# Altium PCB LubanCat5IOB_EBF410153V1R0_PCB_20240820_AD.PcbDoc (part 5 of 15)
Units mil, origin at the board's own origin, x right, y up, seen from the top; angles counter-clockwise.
Board outline 6811.02 x 4055.12 mil, 6 copper layers (TOP, GND02, ART03, ART04, PWR05, BOTTOM), stack 59.279 mil thick; 981 components, 783 nets, 3627 pads, 2669 vias.
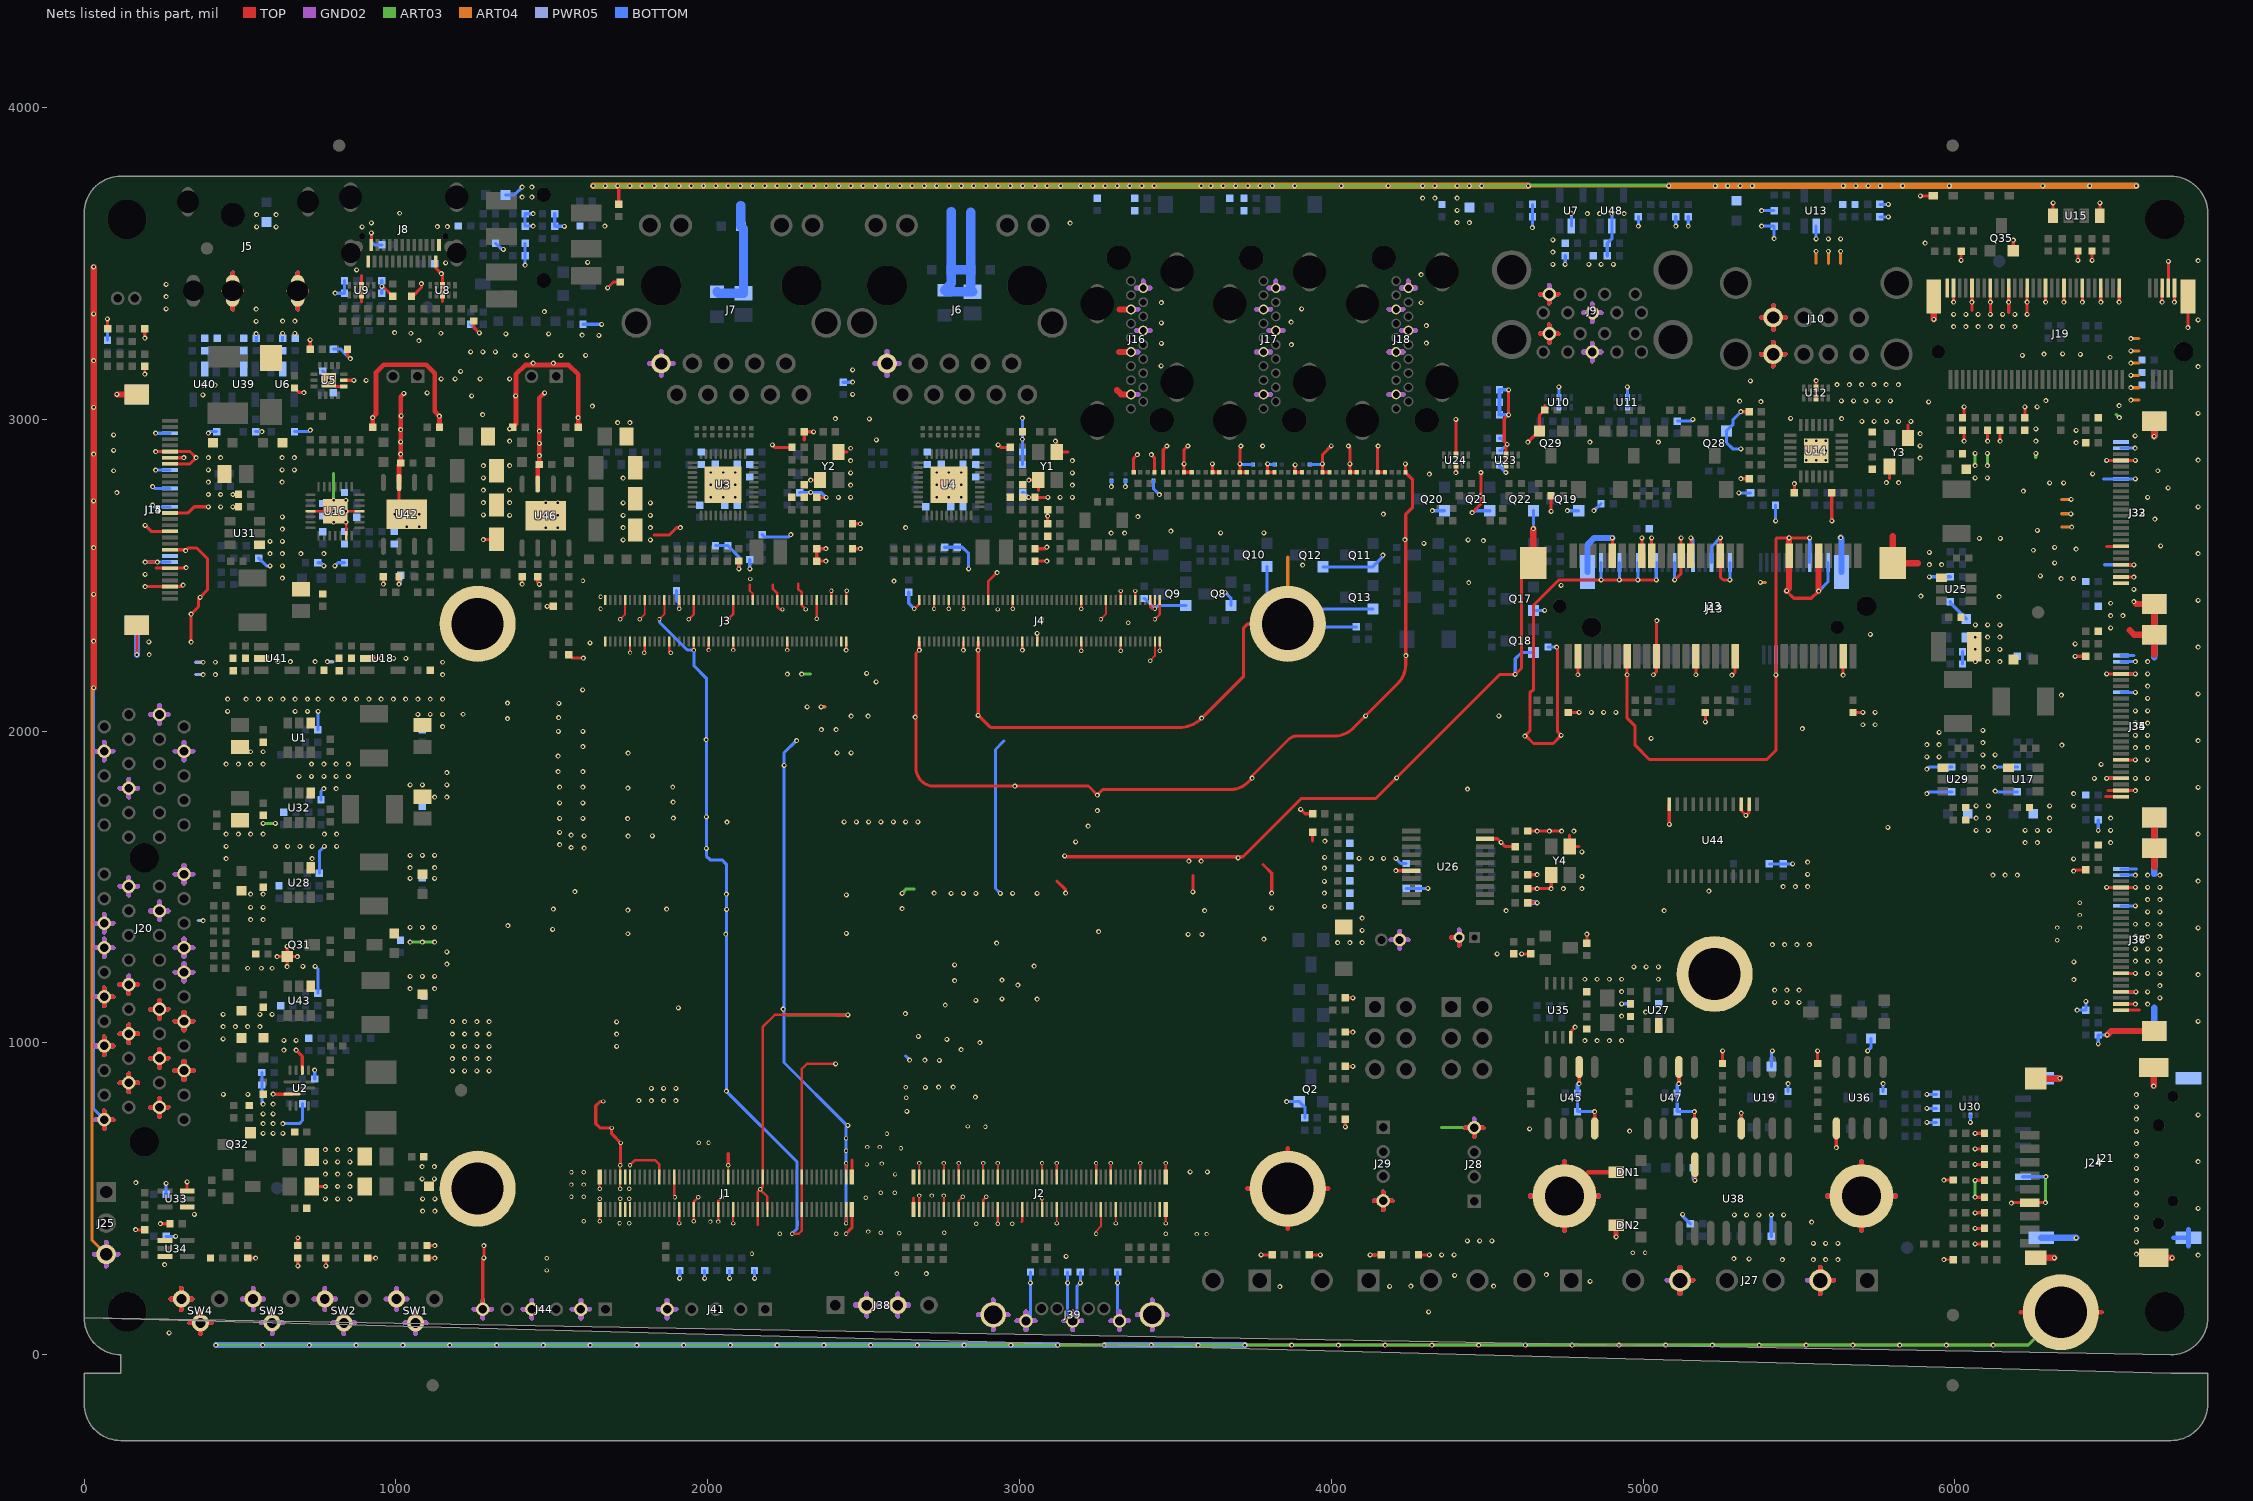
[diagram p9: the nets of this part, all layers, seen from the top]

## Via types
v1: diameter 16, hole 8, TOP to BOTTOM, 2357 vias
v2: diameter 14, hole 8, TOP to BOTTOM, 308 vias
v3: diameter 20, hole 10, TOP to BOTTOM, 4 vias

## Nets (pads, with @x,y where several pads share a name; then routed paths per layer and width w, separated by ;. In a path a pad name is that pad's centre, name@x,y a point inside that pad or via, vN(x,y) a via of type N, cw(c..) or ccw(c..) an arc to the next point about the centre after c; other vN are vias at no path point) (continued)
GND: C1.2 C2.2 C3.2 C4.2 C5.2 C8.2 C9.2 C10.2 C11.2 C12.2 C13.2 C15.2 C17.2 C18.2 C19.2 C21.2 C22.2 C23.2 C24.2 C25.2 C26.2 C27.2 C28.2 C29.2 C30.2 C31.2 C32.2 C33.2 C34.2 C35.2 C36.2 C37.2 C38.2 C39.2 C40.2 C41.2 C42.2 C43.2 C44.2 C45.2 C46.2 C47.2 C48.2 C49.2 C50.2 C51.2 C52.2 C53.2 C54.2 C55.2 C56.2 C57.2 C58.2 C59.2 C60.2 C61.2 C62.2 C63.2 C64.2 C65.2 C66.2 C67.2 C68.2 C69.2 C70.2 C71.2 C72.2 C73.2 C74.2 C77.2 C78.2 C81.2 C86.2 C87.2 C88.2 C89.2 C90.2 C91.2 C92.2 C93.2 C94.2 C95.2 C96.2 C97.2 C98.2 C99.2 C100.2 C101.2 C102.2 C103.2 C104.2 C105.2 C106.2 C107.2 C108.2 C109.2 C110.2 C111.2 C114.2 C116.2 C118.2 C119.2 C120.2 C121.2 C123.2 C124.2 C125.2 C129.2 C130.2 C141.2 C153.2 C155.2 C158.2 C159.2 C160.2 C161.2 C162.2 C163.2 C164.2 C165.2 C166.2 C167.2 C168.2 C169.2 C170.2 C171.2 C172.2 C173.2 C174.2 C180.2 C181.2 C182.2 C183.2 C184.2 C185.2 C186.2 C187.2 C188.2 C193.2 C195.2 C196.2 C197.2 C198.2 C201.2 C202.2 C203.2 C204.2 C205.2 C206.2 C207.2 C208.2 C209.2 C210.2 C211.2 C212.2 C213.2 C216.2 C217.2 C218.2 C219.2 C220.2 C221.2 C222.2 C223.2 C226.2 C227.2 C228.2 C229.2 C230.2 C231.2 C233.2 C234.2 C235.2 C236.2 C237.2 C238.2 C239.2 C240.2 C241.2 C242.2 C243.2 C244.2 C245.2 C246.2 C249.2 C250.2 C253.2 C254.2 C255.2 C256.2 C257.2 C258.2 C259.2 C260.2 C261.2 C262.2 C263.2 C264.2 C265.2 C266.2 C267.2 C268.2 C269.2 C270.2 C271.2 C272.2 C273.2 C274.2 C275.2 C276.2 C277.2 C278.2 C280.2 C281.2 C282.2 C284.2 C285.2 C286.2 C288.2 C289.2 C291.2 C292.2 C293.2 C294.2 C299.1 C300.2 C301.2 C302.2 C303.2 C304.2 C305.2 C306.2 C307.2 C309.1 C310.2 C311.2 C312.2 C313.2 C314.2 C315.2 C316.2 D1.1 D2.1 D3.1 D4.1 D5.1 D6.1 D8.1 D9.1 D10.1 D11.1 D12.1 D13.1 D14.1 D15.2 D16.1 D17.1 D18.1 D19.1 D20.1 D21.1 D22.1 D23.2 D24.2 D25.2 D27.1 D28.1 D29.1 D30.1 D31.1 D32.1 D34.1 D35.1 D36.1 D37.1 D38.1 D39.1 D41.1 D42.1 D43.1 D44.1 D45.1 D47.2 D48.2 D50.1 D51.1 D52.1 D53.1 D54.1 D55.2 D56.2 D59.2 D61.2 D62.2 D63.2 D64.2 D65.1 D66.1 D67.1 D68.1 D69.1 D70.1 D71.1 D72.1 D73.1 D74.1 D75.1 D76.1 D77.1 D78.1 D79.1 D80.1 D81.1 D82.1 D83.1 D85.1 D86.1 D87.1 D88.1 DN1.3 DN2.3 J1.7 J1.8 J1.9 J1.10 J1.11 J1.12 J1.23 J1.29 J1.32 J1.38 J1.48 J1.51 J1.54 J1.64 J1.65 J1.68 J1.81 J1.82 J1.99 J1.100 J1.101 J1.102 J1.103 J1.104 J2.1 J2.2 J2.11 J2.12 J2.17 J2.18 J2.27 J2.28 J2.33 J2.34 J2.44 J2.51 J2.52 J2.57 J2.58 J2.73 J2.76 J2.79 J2.82 J2.91 J2.100 J2.101 J2.102 J2.103 J2.104 J3.1 J3.2 J3.10 J3.11 J3.17 J3.18 J3.26 J3.27 J3.32 J3.37 J3.38 J3.43 J3.53 J3.54 J3.62 J3.72 J3.75 J3.82 J3.88 J3.94 J3.97 J3.99 J3.100 J4.1 J4.2 J4.8 J4.14 J4.19 J4.20 J4.25 J4.30 J4.40 J4.43 J4.49 J4.67 J4.68 J4.78 J4.83 J4.84 J4.90 J4.96 J4.97 J4.98 J4.99 J4.100 J5.2 J5.3 J6.10 J7.10 J8.A1 J8.A12 J8.B1 J8.B12 J9.4 J9.7 J9.13 J9.16 J10.4 J10.10 J12.2 J13.1 J13.7 J13.18 J13.33 J13.39 J13.45 J13.51 J13.57 J13.63 J13.69 J13.75 J13.76 J13.77 J14.6 J14.7 J14.8 J14.16 J14.19 J14.22 J14.25 J14.28 J14.31 J14.32 J15.6 J15.7 J15.8 J15.16 J15.19 J15.22 J15.25 J15.28 J15.31 J15.32 J16.2 J16.5 J16.8 J16.11 J16.17 J17.2 J17.5 J17.8 J17.11 J17.17 J18.2 J18.5 J18.8 J18.11 J18.17 J19.1 J19.3 J19.9 J19.15 J19.21 J19.27 J19.33 J19.39 J19.45 J19.51 J19.57 J19.71 J19.73 J19.75 J19.76 J19.77 J20.A1 J20.A4 J20.A12 J20.A15 J20.A18 J20.A20 J20.A23 J20.A24 J20.A27 J20.A28 J20.A31 J20.B4 J20.B7 J20.B13 J20.B16 J20.B18 J20.B21 J20.B22 J20.B25 J20.B26 J20.B29 J20.B32 J21.5 J21.8 J21.9 J21.10 J21.11 J23.4 J23.9 J23.15 J23.18 J23.21 J23.26 J23.27 J23.29 J23.34 J23.35 J23.37 J23.40 J23.43 J23.50 J23.53 J23.54 J24.6 J24.10 J24.11 J24.12 J24.13 J25.3 J26.2 J27.2 J27.5 J28.4 J29.4 J32.4 J32.18 J32.21 J32.23 J32.24 J32.25 J32.26 J33.4 J33.18 J33.21 J33.23 J33.24 J33.25 J33.26 J34.4 J34.18 J34.21 J34.23 J34.24 J34.25 J34.26 J35.4 J35.18 J35.21 J35.23 J35.24 J35.25 J35.26 J36.4 J36.18 J36.21 J36.23 J36.24 J36.25 J36.26 J37.4 J37.18 J37.21 J37.23 J37.24 J37.25 J37.26 J38.2 J38.3 J39.1 J39.4 J39.7 J39.S1 J39.S2 J41.5 J44.2 J44.4 J44.6 L1.2 L11.2 L12.2 L13.2 LED1.1 Q2.2 Q8.2 Q9.2 Q10.2 Q11.2 Q12.2 Q13.2 Q17.2 Q18.2 Q19.2 Q20.2 Q21.2 Q22.2 Q28.2 Q29.2 Q31.2 Q32.2 Q35.2 R7.2 R16.2 R17.2 R18.2 R25.2 R30.2 R31.2 R32.2 R38.2 R39.2 R40.2 R42.2 R43.2 R44.2 R53.2 R58.2 R59.2 R60.2 R66.2 R68.2 R71.2 R72.2 R78.1 R95.2 R97.2 R98.2 R99.2 R103.2 R108.2 R117.1 R118.2 R123.2 R135.2 R136.2 R139.2 R141.2 R149.2 R156.2 R160.2 R171.2 R177.2 R181.2 R192.2 R194.2 R195.2 R211.2 R219.2 R220.2 R222.2 R227.2 R231.2 R232.2 R233.2 R234.2 R240.2 R241.2 R244.2 R245.2 R250.2 R252.2 R257.2 R261.2 R263.2 R271.2 R274.2 R289.2 R292.2 R295.2 R296.2 R307.2 R308.2 R309.2 R310.2 R317.2 R321.2 R322.2 R323.2 R325.2 R327.2 R335.2 R337.2 R346.2 R352.2 SS5.1 SS6.1 SS7.1 SS8.1 SS9.1 SS10.1 SS11.1 SS12.1 SW1.1 SW1.3 SW2.1 SW2.3 SW3.1 SW3.3 SW4.1 SW4.3 U1.1 U2.2 U2.10 U3.41 U4.41 U5.8 U5.9 U5.15 U6.2 U7.2 U8.3 U8.8 U9.3 U9.8 U10.3 U10.8 U11.3 U11.8 U12.3 U12.8 U13.2 U14.25 U15.1 U15.4 U16.4 U16.13 U16.18 U16.29 U17.1 U18.2 U19.5 U23.3 U23.8 U24.3 U24.8 U25.1 U26.9 U26.16 U27.2 U28.1 U29.1 U30.2 U31.1 U32.1 U33.1 U33.3 U34.1 U34.3 U35.4 U36.5 U38.15 U39.2 U40.2 U41.2 U42.7 U42.9 U43.1 U44.2 U44.3 U44.12 U45.2 U45.8 U46.7 U46.9 U47.2 U47.8 U48.2 Y1.2 Y1.4 Y2.2 Y2.4 Y3.2 Y3.4 Y4.2 Y4.4 | length 117215
  TOP w6: v2(1653.44,427.58) J1.102@1653.44,465.62 ; v2(1653.44,531.91) J1.101@1653.44,569.96 ; v2(1719.39,531.91) J1.7@1719.39,569.96 v2(1719.39,608) ; v2(1719.39,2359) 1735.14,2374.75 J3.10@1735.14,2420.74 ; v2(1782.39,2359) 1798.13,2374.75 J3.18@1798.13,2420.74 ; v2(1845.38,2359) 1861.13,2374.75 J3.26@1861.13,2420.74 ; v2(2034.35,427) J1.48@2034.35,465.62 ; J1.51@2065.85,569.96 v2(2065.85,608) ; v2(2081.59,420.89) J1.54@2081.59,465.62 ; J2.1@2678.74,569.96 v2(2678.74,614.69) ; v2(2725.99,2392) J4.8@2725.99,2420.74 ; J2.12@2757.49,465.62 v2(2757.48,510.36) ; J2.11@2757.49,569.96 v2(2757.48,614.69) ; v2(2773.24,2392) J4.14@2773.24,2420.74 ; J2.18@2804.73,465.62 2804.73,493.73 v2(2818,507) ; J2.17@2804.73,569.96 v2(2804.73,614.69) ; v2(2820.48,2392) J4.20@2820.48,2420.74 ; J2.27@2883.47,569.96 v2(2883.47,614.69) ; J2.33@2930.71,569.96 v2(2930.71,614.69) ; v2(2977.96,2392) J4.40@2977.96,2420.74 ; J2.52@3072.45,465.62 v2(3072.45,501.25) ; J2.51@3072.45,569.96 v2(3072.45,614.69) ; v2(3119.69,420.89) J2.58@3119.69,465.62 ; v2(3198.43,2258.14) J4.67@3198.43,2286.88 ; v2(3245.68,387.89) 3245.68,395.67 3261.42,411.42 J2.76@3261.42,465.62 ; v2(3261.43,2359) 3277.18,2374.75 J4.78@3277.18,2420.74 ; v2(3308.67,420.89) J2.82@3308.67,465.62 ; v2(3324.42,2258.14) J4.83@3324.42,2286.88 ; v2(3418.91,2225.14) 3434.66,2240.89 J4.97@3434.66,2286.88 ; v2(3450.4,2258.14) J4.99@3450.4,2286.88
  TOP w6.8: v1(5965,305) C9.2@5995.32,305
  TOP w8: v1(195,3145) R136.2@195,3169.69 ; U16.4@726.26,2705 v1(800,2705) ; v1(840,2670) 840.43,2669.57 U16.13@840.43,2626.26 ; v1(840,2705) U16.18@883.74,2705 ; v2(1750.88,608) 1766.65,623.77 1831.23,623.77 1845.37,609.63 J1.23@1845.37,569.96 ; J3.11@1750.89,2286.88 1750.89,2252.11 v2(1751,2252) ; v2(1797,2251) 1798.13,2252.13 J3.17@1798.13,2286.88 ; J3.27@1876.88,2286.88 1876.88,2255.12 v2(1881,2251) ; J1.29@1892.62,569.96 1892.62,507.38 v2(1895,505) ; v2(1908.37,420.89) J1.32@1908.37,465.62 ; v2(1908.37,2392) J3.32@1908.37,2420.74 ; v2(1939.87,2359) 1955.62,2374.75 J3.38@1955.62,2420.74 ; v2(1955,428) 1955.61,428.61 J1.38@1955.61,465.62 1955.61,490.61 v2(1970,505) ; v2(1955.62,2260) J3.37@1955.62,2286.88 ; v2(2002.86,2260) J3.43@2002.86,2286.88 ; J1.48@2034.35,465.62 2034.35,494.35 v2(2045,505) ; v2(2065.85,2359) 2081.6,2374.75 J3.54@2081.6,2420.74 ; v2(2081.6,2260) J3.53@2081.6,2286.88 ; 2135,2470 2135,2450 2144.59,2440.41 J3.62@2144.59,2420.74 ; 2160.33,416.67 J1.64@2160.33,465.62 2160.33,522.13 v2(2168.21,530) ; J1.68@2191.83,465.62 2191.83,506.38 v2(2168.21,530) ; 2208,2470 2208,2457 2223.33,2441.67 J3.72@2223.33,2420.74 2223.33,2398 2231.33,2390 v2(2240,2390) ; v2(2254.83,2260) J3.75@2254.83,2286.88 ; v2(2270.57,387.89) 2292.07,387.89 2302.07,397.89 J1.82@2302.07,465.62 J1.81@2302.07,569.96 2302.07,917 2318.07,933 2410.15,933 v1(2410.63,932.52) ; 2290,2472 2290,2456 2302.07,2443.93 J3.82@2302.07,2420.74 2302.07,2402.93 v2(2315,2390) ; J3.88@2349.32,2420.74 2349.32,2360.68 v2(2350,2360) ; J3.94@2396.56,2420.74 2396.56,2449.56 v2(2397,2450) ; 2410.63,1090 2215,1090 2176.08,1051.08 J1.65@2176.08,569.96 2176.08,537.87 v2(2168.21,530) ; v2(2443.8,420.89) J1.100@2443.8,465.62 ; J1.99@2443.8,569.96 v2(2443.8,614.69) ; v1(2443.8,2260) J3.99@2443.8,2286.88 ; J3.100@2443.8,2420.74 2443.8,2447.8 v2(2446,2450) ; v2(2663,2392) 2678.75,2407.75 J4.2@2678.75,2420.74 ; J2.2@2678.74,465.62 v2(2678.74,510.36) ; v1(2820.48,2260) J4.19@2820.48,2286.88 ; J2.28@2883.47,465.62 2883.47,495.47 v2(2894,506) ; J4.30@2899.22,2420.74 2899.22,2479.22 v1(2928,2508) ; v2(2930,420) 2930.71,420.71 J2.34@2930.71,465.62 ; 3007,426 3009.45,428.45 J2.44@3009.45,465.62 ; v1(3009.46,2260) J4.43@3009.46,2286.88 ; J4.49@3056.7,2286.88 v1(3056.7,2313.76) ; J2.57@3119.69,569.96 v2(3119.69,614.69) ; v2(3198.43,2392) J4.68@3198.43,2420.74 ; J2.73@3245.67,569.96 v2(3245.67,614.69) ; J2.79@3292.92,569.96 v2(3292.92,614.69) ; J4.84@3324.42,2420.74 v2(3324.42,2449.48) ; J4.90@3371.66,2420.74 v2(3371.66,2449.48) ; J2.91@3387.41,569.96 v2(3387.41,614.69) ; J4.96@3418.91,2420.74 3418.91,2400 3426.91,2392 v2(3434.66,2392) J4.98@3434.66,2420.74 ; v2(3434.66,2359) 3450.4,2374.75 J4.100@3450.4,2420.74 ; v2(3469.1,420.89) J2.104@3469.1,465.62 ; J2.103@3469.1,569.96 v2(3469.1,614.69) ; C316.2@4685.32,3030 4685.32,3045.05
  TOP w10: v1(75,3322) 75.32,3321.68 D83.1@75.32,3290 ; v1(165,401.26) 165.94,400.32 C235.2@195,400.32 ; v1(169.61,2245) J14.31@169.61,2339.52 ; v1(194.68,3260.32) D78.1@194.68,3290 ; v1(195.63,2542.06) v1(235,2542.06) ; v1(195.63,2660.17) 215.1,2640.69 J14.19@275.91,2640.69 ; v1(196,2463.52) J14.28@275.91,2463.52 313.52,2463.52 v1(318,2468) ; v1(229.08,2896.39) 229.28,2896.59 J14.6@275.91,2896.59 339.69,2896.59 v1(359.37,2876.91) 339.68,2857.22 J14.8@275.91,2857.22 ; 230.79,2522.58 J14.25@275.91,2522.58 325.58,2522.58 v1(327,2524) ; v1(245,420) C236.2@275.32,420 ; J14.22@275.91,2581.63 323.37,2581.63 v1(326,2579) 334.19,2587.19 361.7,2587.19 396,2552.89 396,2453 v1(372,2429) 367,2424 367,2399 v1(343,2375) v1(343,2285) ; J14.16@275.91,2699.74 333.57,2699.74 353.26,2719.43 v1(398.74,2719.43) ; U33.3@330.43,525.28 v1(330.43,554.57) ; C28.2@524.68,310 v1(550,310) ; v1(605.99,835.36) U2.2@666.38,835.36 ; v1(619,1276.87) Q31.2@651.5,1276.87 ; v1(651.5,1244.37) Q31.2@651.5,1276.87 ; v1(651.5,1309.37) Q31.2@651.5,1276.87 ; C74.2@675,3100.32 689.69,3085.63 v1(705,3085.63) ; v1(680.16,976.53) 699.84,956.84 U2.10@699.84,912.13 ; v1(684,1276.87) Q31.2@651.5,1276.87 ; v1(685.32,285) D4.1@685.32,310 ; C15.2@685.32,350 v1(685.32,375) ; C72.2@725.32,3225 v1(725.32,3254.68) ; C281.2@730.04,539.37 v1(774,539.37) ; v1(775.32,285) C5.2@775.32,310 ; v1(785,3125) 804.68,3105.32 U5.8@832.64,3105.32 ; C73.2@844.68,3225 844.68,3203.75 v1(853.9,3194.53) ; 890,3377 U9.3@890,3398.62 U9.8@890,3430.12 890,3461.16 ; U18.2@908.42,2233 v1(953,2233) ; D3.1@909.68,310 v1(934.68,310) ; J8.B1@921.26,3559.05 v1(921.26,3598.19) ; v1(955,3426) 958.69,3426 D9.1@990,3394.69 ; v1(960,2471) R346.2@960,2495.32 ; v1(1010,2471) C302.2@1010,2495.32 ; U42.7@1010,2797.36 1010,2720 v1(1035,2695) ; D8.1@1050,3394.69 1053.69,3394.69 1082,3423 v1(1082,3435) ; D2.1@1099.68,310 v1(1124.68,310) ; C4.2@1099.68,350 v1(1124.68,350) ; J8.A1@1127.95,3506.3 1127.95,3485.42 v1(1146,3467.37) 1150,3463.37 U8.8@1150,3430.12 U8.3@1150,3398.62 1150,3378 ; D80.1@1250,3315.32 1250,3294.69 v1(1267.85,3276.84) ; J44.6@1278.54,145.66 1278.54,307.01 v1(1282.16,310.63) v1(1282.16,350) ; v1(1280.98,2614) 1281.98,2615 C211.2@1322.99,2615 ; v1(1405,2471) R352.2@1405,2495.32 ; C312.2@1455,2495.32 1455,2476 1460,2471 v1(1460,2470.52) ; v1(1485,2400.32) C309.1@1505,2400.32 ; R337.2@1555,2245.32 1566.32,2234 v1(1601,2234) ; v2(1665,812.08) 1655.08,812.08 1640.94,797.94 1640.94,741.06 1655.08,726.92 1691.92,726.92 v2(1692,727) 1692,708 v2(1721,679) 1721,609.61 v2(1719.39,608) ; v1(1678.84,3421.26) 1697.9,3440.32 D79.1@1720,3440.32 ; 1828,2629 1877,2629 1900.2,2652.2 v1(1912.22,2652.2) ; v2(2065.85,608) 2065.85,644.85 ; v1(2100,2520) C69.2@2100,2545.32 ; v1(2207.39,2917.8) 2215.19,2910 C54.2@2270.32,2910 ; 2309.68,2933.68 C67.2@2309.68,2960 v1(2340,2960) ; v1(2330.28,2804.72) Y2.2@2360.47,2804.72 ; C60.2@2350,2749.68 v1(2379.68,2749.68) ; v1(2379.36,2545) C53.2@2349.68,2545 C52.2@2349.68,2585 v1(2379.36,2585) ; 2410.63,1090 v1(2450,1090) ; Y2.4@2419.53,2895.28 2446.54,2895.28 ; v2(2443.8,387.89) 2462.5,406.59 J1.104@2462.5,465.62 ; J1.103@2462.5,569.96 2462.5,623.5 ; R78.1@2464.68,2585 v1(2490,2585) ; C59.2@2464.68,2665 v1(2490,2665) ; J2.102@2660.04,465.62 2660.04,502.96 ; J4.1@2678.75,2286.88 v1(2678.75,2260) 2668,2249.25 2668,1882.92 ccw(c2728.91,1882.92) 2685.84,1839.85 ccw(c2724.11,1878.11) 2724.11,1824 2984.74,1824 v1(2985,1823.74) 3221.26,1823.74 v1(3250,1795) 3268,1813 3679.72,1813 ccw(c3679.72,1886.11) 3731.41,1834.41 v1(3746,1849) 3746,1856 3863.03,1973.03 cw(c3889.52,1946.53) 3889.52,1984 4008.53,1984 ccw(c4008.53,2072.06) 4070.79,2009.79 v1(4110,2049) 4213.7,2152.7 ccw(c4152.64,2213.77) 4239,2213.77 v1(4239,2242) 4239,2695 4260,2716 4260,2807.83 D73.1@4237.83,2830 v1(4237.83,2857) ; J4.25@2867.73,2286.88 v1(2867.73,2260) v1(2867.73,2050.27) 2901.14,2016.86 ccw(c2915.28,2031) 2915.28,2011 3510.87,2011 ccw(c3510.87,2115.13) v1(3584.5,2041.5) 3719,2176 3719,2331 3731.81,2343.81 SS6.1@3860.49,2343.81 ; v1(2931.8,2917.8) 2939.6,2910 C33.2@2970.32,2910 ; C39.2@3010,2749.68 v1(3029.68,2749.68) C42.2@3050,2749.68 v1(3091,2749.68) ; v1(3030.28,2804.72) Y1.2@3060.47,2804.72 3060.47,2771.47 ; C32.2@3049.68,2545 v1(3088,2545) ; C31.2@3049.68,2585 3083,2585 v1(3088,2590) ; C49.2@3090.32,2665 v1(3090.32,2689.68) C48.2@3090.32,2710 ; v1(3115,2930) 3119.53,2925.47 Y1.4@3119.53,2895.28 3154.72,2895.28 ; 3120,1519 3148,1491 v1(3148,1480) ; v1(3145,1600) 3148,1597 3717.07,1597 3903.82,1783.75 4142.75,1783.75 4541,2182 v1(4590,2182) 4610,2202 4610,2501 J23.53@4647.64,2538.64 ; D27.1@3366.17,2830 3366.17,2874.67 v1(3378.5,2887) ; v1(3422.87,2887) 3432.83,2877.04 D30.1@3432.83,2830 ; D5.1@3461.17,2830 3461.17,2902.54 v1(3473,2914.37) ; v1(3540,2914.37) 3527.83,2902.2 v1(3527.83,2857) D14.1@3527.83,2830 D50.1@3552.17,2830 ; v1(3556,1484) 3556,1536 ; v1(3618.83,2857) D51.1@3618.83,2830 D52.1@3641.17,2830 ; v1(3710,2914.37) 3706.83,2911.2 v1(3706.83,2857) D53.1@3706.83,2830 D54.1@3729.17,2830 ; v1(3775,320) D74.1@3810.32,320 ; 3781,1572 3809,1544 v1(3809,1480.12) ; v1(3795.83,2857) D65.1@3795.83,2830 D34.1@3818.17,2830 ; v1(3883.83,2854) D37.1@3883.83,2830 D66.1@3906.17,2830 ; v1(3902,1749) 3916,1735 R245.2@3940.32,1735 ; D75.1@3929.68,320 v1(3965,320) ; 3940.32,1647 R244.2@3940.32,1675 ; D68.1@3994.17,2830 D67.1@3971.83,2830 v1(3971.83,2857) 3971.83,2886.83 v1(4000,2915) ; v1(4045,730.64) D63.2@4045,755.32 ; D64.2@4045,924.68 v1(4069.68,924.68) ; D61.2@4045,1034.68 v1(4069.68,1034.68) ; D62.2@4045,1144.68 v1(4069.68,1144.68) ; v1(4055,2914.37) 4059.83,2909.54 v1(4059.83,2857) D69.1@4059.83,2830 D70.1@4082.17,2830 ; v1(4125,320) D76.1@4160.32,320 ; v1(4150,2914.37) 4148.83,2913.2 D71.1@4148.83,2830 D72.1@4172.17,2830 ; v1(4207.2,1552.2) U26.16@4256.89,1552.2 ; D77.1@4279.68,320 v1(4315,320) ; v1(4400,2829) U24.3@4400,2853.62 ; U24.8@4400,2885.12 v1(4400,3000) ; v1(4452,2700.37) 4480,2728.37 v1(4480,2829.37) ; U26.9@4493.11,1654.57 4533.19,1654.57 v1(4545,1642.76) 4558.39,1629.37 C165.2@4590.32,1629.37 ; U23.3@4560,2853.62 U23.8@4560,2885.12 4560,2919.37 v1(4564.48,2919.37) 4555,2928.85 4555,3000.84 v1(4568.53,3014.37) v1(4568.53,3094.37) ; v1(4610.74,1285.32) C238.2@4640,1285.32 ; C163.2@4629.68,1449.37 v1(4660,1449.37) ; R233.2@4629.68,1494.37 v1(4660,1494.37) 4660.47,1494.84 v1(4705.47,1494.84) Y4.4@4705.47,1539.09 ; C164.2@4629.68,1539.37 v1(4660,1539.37) ; R234.2@4629.68,1679.37 v1(4660,1679.37) v1(4699.37,1679.37) v1(4738.74,1679.37) ; v1(4630.63,2926.87) 4666.63,2962.87 Q29.2@4667.5,2962.87 4667.5,3012.18 C316.2@4685.32,3030 ; v1(4705,2704.37) R194.2@4705,2754.69 ; v1(4722.68,2269.68) 4726,2266.36 4726,1998 v1(4737.56,1986.44) 4711.48,1960.37 4648.52,1960.37 4624.89,1984 v1(4621,1984) 4637.2,2000.2 4637.2,2122.57 4649,2134.37 4649,2404.35 4729.26,2484.61 v1(4865.24,2484.61) v1(4924.29,2484.61) v1(4983.35,2484.61) v1(5042.4,2484.61) ; C220.2@4760,2059.69 v1(4794.68,2059.69) ; 4764.53,1666.47 Y4.2@4764.53,1629.65 4793.65,1629.65 ; U35.4@4768.39,1018.39 4768.39,1036.43 v1(4782.16,1050.2) ; v1(4791.34,2180.71) J23.50@4791.34,2239.43 ; C237.2@4820,1319.68 v1(4820,1349) ; J23.43@4901.58,2562.26 v1(4901.58,2619.63) ; J23.40@4948.82,2239.43 v1(4948.82,2180.71) 4948.82,2114.83 4949,2114.65 4949,2041.37 4974.7,2015.67 4974.7,1954.41 5020.34,1908.77 5358.54,1908.77 5396.77,1908.77 5426.26,1938.26 v1(5426.26,2180.11) 5426.26,2616.63 5429,2619.37 v1(5468.51,2619.37) v1(5534.53,2619.37) ; J23.37@4996.06,2562.26 v1(4996.06,2619.63) ; J23.35@5027.56,2562.26 v1(5027.56,2619.63) ; v1(5033.31,2180.71) 5043.31,2190.71 J23.34@5043.31,2239.43 5043.31,2353.68 v1(5044,2354.37) ; v1(5084.25,1700.75) U44.12@5084.25,1766.14 ; v1(5101.46,2484.61) 5122.05,2505.2 J23.29@5122.05,2562.26 v1(5122.05,2619.63) ; J23.27@5153.55,2562.26 v1(5153.55,2619.63) ; U47.8@5165,725.95 v1(5165,779.37) ; v1(5169.29,2180.71) J23.26@5169.29,2239.43 ; v1(5200,2029.37) C221.2@5200,2059.69 ; v1(5248.03,2619.63) J23.21@5248.03,2562.26 5248.03,2494.34 5257.76,2484.61 v1(5278.62,2484.61) ; R296.2@5255,934.05 v1(5255,974.37) ; v1(5285,2179.37) 5295.28,2189.65 J23.18@5295.28,2239.43 ; v1(5314,3024.37) R108.2@5340.32,3024.37 ; U44.3@5314.57,1766.14 5314.57,1745.43 v1(5330,1730) 5340.16,1740.16 U44.2@5340.16,1766.14 ; v1(5460.27,2449.37) 5483.64,2426 5539.99,2426 v1(5562.99,2449) ; C95.2@5485.32,2764.37 v1(5485.32,2794.05) ; U12.3@5555,3068.62 U12.8@5555,3100.12 v1(5555,3124.37) ; R292.2@5560,934.05 v1(5560,974.37) ; v1(5605.32,2674.37) C96.2@5605.32,2764.37 ; v1(5641.73,2179.37) J23.4@5641.73,2239.43 ; C223.2@5673.23,2059.69 v1(5705,2059.69) ; 5790.47,2810.9 Y3.4@5790.47,2849.09 ; Y3.2@5849.53,2939.65 5849.53,2980.9 ; v1(5889.17,3716.54) LED1.1@5931.25,3716.54 ; v1(5965,560) C10.2@5995.32,560 ; v1(5995.75,3376.14) J19.3@5995.75,3421.65 ; v1(6020.32,3509.37) R335.2@6020.32,3539.37 ; C171.2@6024.68,2965 6029.68,2960 v1(6029.68,2930) ; C170.2@6024.68,3005 6029.68,3010 v1(6029.68,3040) ; 6054.81,3349.81 v1(6054.81,3376.14) J19.9@6054.81,3421.65 ; v1(6065,355) D16.1@6095.32,355 ; v1(6065,405) D17.1@6095.32,405 ; v1(6065,455) D18.1@6095.32,455 ; v1(6065,505) D19.1@6095.32,505 ; v1(6065,559.29) D23.2@6095.32,559.29 ; v1(6065,610) D20.1@6095.32,610 ; v1(6065,660) D21.1@6095.32,660 ; v1(6065,710) D22.1@6095.32,710 ; v1(6105,2930.32) C182.2@6105,2965.32 ; v1(6113.86,3336.77) v1(6113.86,3376.14) J19.15@6113.86,3421.65 ; v1(6145,2930.32) C183.2@6145,2965.32 ; 6172.92,3343.08 v1(6172.92,3376.14) J19.21@6172.92,3421.65 ; v1(6181,486) 6182.68,487.68 J24.6@6240.06,487.68 v1(6290.79,487.68) ; Q35.2@6187.5,3540.87 v1(6187.5,3574.37) ; C169.2@6224.68,3005 v1(6224.68,3040) ; v1(6231.97,3336.77) v1(6231.97,3376.14) J19.27@6231.97,3421.65 ; v1(6291.03,3376.14) J19.33@6291.03,3421.65 ; U15.4@6315,3653.15 v1(6315,3694.37) ; v1(6350.08,3376.14) J19.39@6350.08,3421.65 ; v1(6380.63,1550.62) 6385.01,1555 C275.2@6420.32,1555 ; v1(6385.63,2240) C271.2@6420.32,2240 ; v1(6395,3509.37) C104.2@6395,3539.69 ; v1(6409.14,3376.14) J19.45@6409.14,3421.65 ; v1(6440,3509.37) C105.2@6440,3539.69 ; U15.1@6465,3653.15 v1(6465,3694.37) ; v1(6468.19,3376.14) J19.51@6468.19,3421.65 ; 6482.93,1789.61 J34.24@6533.11,1789.61 ; v1(6486.97,1498.58) J36.4@6533.11,1498.58 v1(6579.25,1498.58) ; v1(6486.97,1848.66) J34.21@6533.11,1848.66 ; v1(6486.97,2183.31) J34.4@6533.11,2183.31 v1(6579.25,2183.31) ; 6486.97,2592.44 J32.18@6533.11,2592.44 ; v1(6486.97,2868.03) J32.4@6533.11,2868.03 v1(6579.25,2868.03) ; 6491.08,1809.29 J34.23@6533.11,1809.29 v1(6579.25,1809.29) ; v1(6527.25,3376.14) J19.57@6527.25,3421.65 ; J36.24@6533.11,1104.88 6591.49,1104.88 ; J36.23@6533.11,1124.57 v1(6579.25,1124.57) ; J36.21@6533.11,1163.94 v1(6580.35,1163.94) ; J36.18@6533.11,1222.99 v1(6579.25,1222.99) ; J34.18@6533.11,1907.72 v1(6579.25,1907.72) ; J32.23@6533.11,2494.01 v1(6574.25,2494.01) ; J32.21@6533.11,2533.39 v1(6574.25,2533.39) ; v1(6665.04,3376.14) J19.71@6665.04,3421.65 ; J19.73@6684.73,3421.65 v1(6684.73,3506.53) ; v1(6704.41,3376.14) J19.75@6704.41,3421.65 ; v1(6747.72,3294.37) J19.76@6747.72,3394.09
  TOP w12: J14.7@275.91,2876.91 v1(320,2876.91) ; U5.9@832.64,3125 v1(865,3125) ; D81.1@1715,3689.68 1715,3737 ; v1(4795,869.37) U45.2@4795,922.79 ; U45.8@4845,725.95 v1(4845,779.37) ; v1(5115,869.37) U47.2@5115,922.79 ; v1(5166.37,558.97) U38.15@5166.37,609.17 ; v1(5314,2809.37) C98.2@5340.32,2809.37 ; U19.5@5315,725.95 v1(5315,774.52) ; v1(5620,664) U36.5@5620,725.95
  TOP w15: 64.56,725.28 J20.B32@64.56,753.93 ; 64.56,782.59 J20.B32@64.56,753.93 ; 64.56,961.5 J20.B26@64.56,990.15 ; 64.56,1018.81 J20.B26@64.56,990.15 ; 64.56,1118.98 J20.B22@64.56,1147.63 ; 64.56,1176.29 J20.B22@64.56,1147.63 ; 93.22,753.93 J20.B32@64.56,753.93 ; 93.22,990.15 J20.B26@64.56,990.15 ; 93.22,1147.63 J20.B22@64.56,1147.63 ; 114.65,872.04 J20.B29@143.3,872.04 ; 114.65,1029.52 J20.B25@143.3,1029.52 ; 114.65,1187 J20.B21@143.3,1187 ; 143.3,843.39 J20.B29@143.3,872.04 ; 143.3,900.7 J20.B29@143.3,872.04 ; 143.3,1000.87 J20.B25@143.3,1029.52 ; 143.3,1058.18 J20.B25@143.3,1029.52 ; 143.3,1158.35 J20.B21@143.3,1187 ; 171.96,872.04 J20.B29@143.3,872.04 ; 171.96,1029.52 J20.B25@143.3,1029.52 ; 171.96,1187 J20.B21@143.3,1187 ; 213.07,793.3 J20.A31@241.73,793.3 ; 213.07,950.78 J20.A27@241.73,950.78 ; 213.07,1108.26 J20.A23@241.73,1108.26 ; 241.73,764.65 J20.A31@241.73,793.3 ; 241.73,821.96 J20.A31@241.73,793.3 ; 241.73,922.13 J20.A27@241.73,950.78 ; 241.73,979.44 J20.A27@241.73,950.78 ; 241.73,1079.61 J20.A23@241.73,1108.26 ; 241.73,1136.92 J20.A23@241.73,1108.26 ; 270.38,793.3 J20.A31@241.73,793.3 ; 270.38,950.78 J20.A27@241.73,950.78 ; 270.38,1108.26 J20.A23@241.73,1108.26 ; 277.53,178.81 SW4.1@312.09,178.81 ; 291.81,911.41 J20.A28@320.47,911.41 ; 291.81,1068.89 J20.A24@320.47,1068.89 ; 312.09,144.25 SW4.1@312.09,178.81 ; 312.09,213.38 SW4.1@312.09,178.81 ; 320.47,882.76 J20.A28@320.47,911.41 ; 320.47,940.07 J20.A28@320.47,911.41 ; 320.47,1040.24 J20.A24@320.47,1068.89 ; 320.47,1097.55 J20.A24@320.47,1068.89 ; 338.55,102.04 SW4.3@373.11,102.04 ; 346.65,178.81 SW4.1@312.09,178.81 ; 349.12,911.41 J20.A28@320.47,911.41 ; 349.12,1068.89 J20.A24@320.47,1068.89 ; 373.11,67.48 SW4.3@373.11,102.04 ; 373.11,136.6 SW4.3@373.11,102.04 ; 407.67,102.04 SW4.3@373.11,102.04 ; 447.72,3412.17 J5.2@476.37,3412.17 ; 476.37,3353.97 J5.2@476.37,3412.17 ; 476.37,3470.37 J5.2@476.37,3412.17 ; 505.02,3412.17 J5.2@476.37,3412.17 ; 656.32,3412.17 J5.3@684.97,3412.17 ; 684.97,3353.97 J5.3@684.97,3412.17 ; 684.97,3470.37 J5.3@684.97,3412.17 ; 713.62,3412.17 J5.3@684.97,3412.17 ; C300.2@925.32,2975 v1(925.32,3005.68) 936,3016.36 936,3150 961,3175 1097.5,3175 1124.5,3148 1124.5,3025.18 v1(1139.68,3010) C301.2@1139.68,2975 ; U42.7@1010,2797.36 1010,2854.68 C278.2@1015.32,2860 v1(1015.31,2888.32) v1(1015.31,2927.69) v1(1015.31,2967.06) 1015.31,3072.31 v1(1026,3083) ; C310.2@1375.32,2975 1385,2984.68 1385,3144 1415,3174 1554.68,3174 1584.68,3144 v1(1584.68,3005.68) C311.2@1584.68,2975 ; U46.7@1455,2792.36 1455,2849.68 C307.2@1460.32,2855 v1(1460.31,2883.32) v1(1460.31,2922.69) v1(1460.31,2962.06) 1460.31,3068.31 v1(1477,3085) ; 3731.44,532.79 SS8.1@3860.49,532.79 ; 3860.49,403.74 SS8.1@3860.49,532.79 ; 3860.49,661.84 SS8.1@3860.49,532.79 ; 3989.54,532.79 SS8.1@3860.49,532.79 ; 4137.72,493.42 J29.4@4166.38,493.42 ; 4166.38,464.76 J29.4@4166.38,493.42 ; 4166.38,522.08 J29.4@4166.38,493.42 ; 4195.03,493.42 J29.4@4166.38,493.42 ; 4385.71,1338.42 J26.2@4410.43,1338.42 4410.43,1313.7 ; 4429.97,728.11 J28.4@4458.62,728.11 ; 4458.62,699.45 J28.4@4458.62,728.11 ; 4487.28,728.11 J28.4@4458.62,728.11 ; 4638.66,509.17 SS9.1@4748.02,509.17 ; 4670.99,3274.86 J9.13@4699.64,3274.86 ; 4670.99,3400.86 J9.4@4699.64,3400.86 ; 4699.64,3246.21 J9.13@4699.64,3274.86 ; 4699.64,3303.52 J9.13@4699.64,3274.86 ; 4699.64,3372.21 J9.4@4699.64,3400.86 ; 4728.3,3274.86 J9.13@4699.64,3274.86 ; 4728.3,3400.86 J9.4@4699.64,3400.86 ; 4748.02,399.81 SS9.1@4748.02,509.17 ; 4748.02,618.53 SS9.1@4748.02,509.17 ; 4857.38,509.17 SS9.1@4748.02,509.17 ; v1(4913.5,378) DN2.3@4913.5,415 ; DN1.3@4913.5,585 4823.85,585 SS9.1@4748.02,509.17 ; 5118.74,195.75 J27.5@5118.74,238.19 ; 5118.74,280.62 J27.5@5118.74,238.19 ; SS12.1@5120.05,1220.89 SS12.1@5229.41,1220.89 ; 5161.17,238.19 J27.5@5118.74,238.19 ; SS12.1@5229.41,1111.52 SS12.1@5229.41,1220.89 ; SS12.1@5229.41,1330.25 SS12.1@5229.41,1220.89 ; SS12.1@5338.77,1220.89 SS12.1@5229.41,1220.89 ; 5378.82,3208.66 J10.4@5417.32,3208.66 ; 5378.82,3326.77 J10.10@5417.32,3326.77 ; 5417.32,3170.16 J10.4@5417.32,3208.66 ; 5417.32,3247.16 J10.4@5417.32,3208.66 ; 5417.32,3288.27 J10.10@5417.32,3326.77 ; 5417.32,3365.27 J10.10@5417.32,3326.77 ; 5455.82,3208.66 J10.4@5417.32,3208.66 ; 5455.82,3326.77 J10.10@5417.32,3326.77 ; 5568.74,195.75 J27.2@5568.74,238.19 ; 5568.74,280.62 J27.2@5568.74,238.19 ; 5591.42,509.17 SS10.1@5700.78,509.17 ; 5611.17,238.19 J27.2@5568.74,238.19 ; 5700.78,399.81 SS10.1@5700.78,509.17 ; 5700.78,618.53 SS10.1@5700.78,509.17 ; 5810.14,509.17 SS10.1@5700.78,509.17 ; 6211.19,136.22 SS11.1@6340.24,136.22 6469.29,136.22
  TOP w20: v1(30.68,2138.49) v1(30.68,2288.49) v1(30.68,2438.49) v1(30.68,2588.49) v1(30.68,2738.49) v1(30.68,2888.49) v1(30.68,3038.49) v1(30.68,3188.49) v1(30.68,3338.49) v1(30.68,3488.49) ; v1(105.3,3079.67) J14.32@169.61,3079.67 ; 3313,3093 3326.3,3079.7 J16.17@3357.72,3079.7 ; 3319.89,3216.11 J16.11@3357.72,3216.11 ; 3320.53,3352.53 J16.5@3357.72,3352.53 ; J23.53@4647.64,2538.64 4647.64,2648.51 v1(4648.5,2649.37) ; v1(5460.27,2449.37) 5468.51,2457.61 J23.15@5468.51,2562.26 v1(5468.51,2619.37) ; v1(5562.99,2449) J23.9@5562.99,2562.26 ; 5801.18,2624.55 J23.54@5801.18,2538.64 5881.73,2538.64 ; v1(5932.76,3320.61) J19.77@5932.76,3394.09 ; J24.10@6259.74,310.51 v1(6319,310.51) ; J24.13@6259.74,885.31 6335.77,885.31 v1(6337,886.54) ; v1(6488.32,1025.32) 6500.95,1037.95 J36.25@6639.49,1037.95 ; 6561,2323.37 6575.08,2309.29 J34.26@6639.49,2309.29 ; 6581.97,2407.4 J32.25@6639.49,2407.4 J34.26@6639.49,2309.29 ; J24.11@6637.7,310.51 v1(6696.95,310.51) ; v1(6637.7,861.5) J24.12@6637.7,920.75 ; 6639.49,1563.88 J36.26@6639.49,1624.57 J34.25@6639.49,1722.68 ; 6639.49,2244.86 J34.26@6639.49,2309.29 ; v1(6639.49,2944.86) J32.26@6639.49,2994.01
  GND02 w15: 32.36,321.89 J25.3@70.86,321.89 ; 35.91,753.93 J20.B32@64.56,753.93 ; 35.91,990.15 J20.B26@64.56,990.15 ; 35.91,1147.63 J20.B22@64.56,1147.63 ; 35.91,1305.11 J20.B18@64.56,1305.11 ; 35.91,1383.85 J20.B16@64.56,1383.85 ; 35.91,1935.04 J20.B4@64.56,1935.04 ; 64.56,725.28 J20.B32@64.56,753.93 ; 64.56,782.59 J20.B32@64.56,753.93 ; 64.56,961.5 J20.B26@64.56,990.15 ; 64.56,1018.81 J20.B26@64.56,990.15 ; 64.56,1118.98 J20.B22@64.56,1147.63 ; 64.56,1176.29 J20.B22@64.56,1147.63 ; 64.56,1276.46 J20.B18@64.56,1305.11 ; 64.56,1333.77 J20.B18@64.56,1305.11 ; 64.56,1355.2 J20.B16@64.56,1383.85 ; 64.56,1412.51 J20.B16@64.56,1383.85 ; 64.56,1906.38 J20.B4@64.56,1935.04 ; 64.56,1963.69 J20.B4@64.56,1935.04 ; 70.86,283.39 J25.3@70.86,321.89 ; 70.86,360.38 J25.3@70.86,321.89 ; 93.22,753.93 J20.B32@64.56,753.93 ; 93.22,990.15 J20.B26@64.56,990.15 ; 93.22,1147.63 J20.B22@64.56,1147.63 ; 93.22,1305.11 J20.B18@64.56,1305.11 ; 93.22,1383.85 J20.B16@64.56,1383.85 ; 93.22,1935.04 J20.B4@64.56,1935.04 ; 109.36,321.89 J25.3@70.86,321.89 ; 114.65,872.04 J20.B29@143.3,872.04 ; 114.65,1029.52 J20.B25@143.3,1029.52 ; 114.65,1187 J20.B21@143.3,1187 ; 114.65,1501.96 J20.B13@143.3,1501.96 ; 114.65,1816.92 J20.B7@143.3,1816.92 ; 143.3,843.39 J20.B29@143.3,872.04 ; 143.3,900.7 J20.B29@143.3,872.04 ; 143.3,1000.87 J20.B25@143.3,1029.52 ; 143.3,1058.18 J20.B25@143.3,1029.52 ; 143.3,1158.35 J20.B21@143.3,1187 ; 143.3,1215.66 J20.B21@143.3,1187 ; 143.3,1473.31 J20.B13@143.3,1501.96 ; 143.3,1530.62 J20.B13@143.3,1501.96 ; 143.3,1788.27 J20.B7@143.3,1816.92 ; 143.3,1845.58 J20.B7@143.3,1816.92 ; 171.96,872.04 J20.B29@143.3,872.04 ; 171.96,1029.52 J20.B25@143.3,1029.52 ; 171.96,1187 J20.B21@143.3,1187 ; 171.96,1501.96 J20.B13@143.3,1501.96 ; 171.96,1816.92 J20.B7@143.3,1816.92 ; 213.07,793.3 J20.A31@241.73,793.3 ; 213.07,950.78 J20.A27@241.73,950.78 ; 213.07,1108.26 J20.A23@241.73,1108.26 ; 213.07,1423.22 J20.A15@241.73,1423.22 ; 213.07,2053.14 J20.A1@241.73,2053.14 ; 241.73,764.65 J20.A31@241.73,793.3 ; 241.73,821.96 J20.A31@241.73,793.3 ; 241.73,922.13 J20.A27@241.73,950.78 ; 241.73,979.44 J20.A27@241.73,950.78 ; 241.73,1079.61 J20.A23@241.73,1108.26 ; 241.73,1136.92 J20.A23@241.73,1108.26 ; 241.73,1394.57 J20.A15@241.73,1423.22 ; 241.73,1451.88 J20.A15@241.73,1423.22 ; 241.73,2024.49 J20.A1@241.73,2053.14 ; 241.73,2081.8 J20.A1@241.73,2053.14 ; 270.38,793.3 J20.A31@241.73,793.3 ; 270.38,950.78 J20.A27@241.73,950.78 ; 270.38,1108.26 J20.A23@241.73,1108.26 ; 270.38,1423.22 J20.A15@241.73,1423.22 ; 270.38,2053.14 J20.A1@241.73,2053.14 ; 277.53,178.81 SW4.1@312.09,178.81 ; 291.81,911.41 J20.A28@320.47,911.41 ; 291.81,1068.89 J20.A24@320.47,1068.89 ; 291.81,1226.37 J20.A20@320.47,1226.37 ; 291.81,1305.11 J20.A18@320.47,1305.11 ; 291.81,1541.33 J20.A12@320.47,1541.33 ; 291.81,1935.04 J20.A4@320.47,1935.04 ; 312.09,144.25 SW4.1@312.09,178.81 ; 312.09,213.38 SW4.1@312.09,178.81 ; 320.47,882.76 J20.A28@320.47,911.41 ; 320.47,940.07 J20.A28@320.47,911.41 ; 320.47,1040.24 J20.A24@320.47,1068.89 ; 320.47,1097.55 J20.A24@320.47,1068.89 ; 320.47,1197.72 J20.A20@320.47,1226.37 ; 320.47,1255.03 J20.A20@320.47,1226.37 ; 320.47,1276.46 J20.A18@320.47,1305.11 ; 320.47,1333.77 J20.A18@320.47,1305.11 ; 320.47,1512.68 J20.A12@320.47,1541.33 ; 320.47,1569.99 J20.A12@320.47,1541.33 ; 320.47,1906.38 J20.A4@320.47,1935.04 ; 320.47,1963.69 J20.A4@320.47,1935.04 ; 338.55,102.04 SW4.3@373.11,102.04 ; 346.65,178.81 SW4.1@312.09,178.81 ; 349.12,911.41 J20.A28@320.47,911.41 ; 349.12,1068.89 J20.A24@320.47,1068.89 ; 349.12,1226.37 J20.A20@320.47,1226.37 ; 349.12,1305.11 J20.A18@320.47,1305.11 ; 349.12,1541.33 J20.A12@320.47,1541.33 ; 349.12,1935.04 J20.A4@320.47,1935.04 ; 373.11,67.48 SW4.3@373.11,102.04 ; 373.11,136.6 SW4.3@373.11,102.04 ; 407.67,102.04 SW4.3@373.11,102.04 ; 447.72,3412.17 J5.2@476.37,3412.17 ; 476.37,3353.97 J5.2@476.37,3412.17 ; 476.37,3470.37 J5.2@476.37,3412.17 ; 505.02,3412.17 J5.2@476.37,3412.17 ; 507.53,178.81 SW3.1@542.09,178.81 ; 542.09,144.25 SW3.1@542.09,178.81 ; 542.09,213.38 SW3.1@542.09,178.81 ; 568.55,102.04 SW3.3@603.11,102.04 ; 576.65,178.81 SW3.1@542.09,178.81 ; 603.11,67.48 SW3.3@603.11,102.04 ; 603.11,136.6 SW3.3@603.11,102.04 ; 637.67,102.04 SW3.3@603.11,102.04 ; 656.32,3412.17 J5.3@684.97,3412.17 ; 684.97,3353.97 J5.3@684.97,3412.17 ; 684.97,3470.37 J5.3@684.97,3412.17 ; 713.62,3412.17 J5.3@684.97,3412.17 ; 737.53,178.81 SW2.1@772.09,178.81 ; 772.09,144.25 SW2.1@772.09,178.81 ; 772.09,213.38 SW2.1@772.09,178.81 ; 798.55,102.04 SW2.3@833.11,102.04 ; 806.65,178.81 SW2.1@772.09,178.81 ; 833.11,67.48 SW2.3@833.11,102.04 ; 833.11,136.6 SW2.3@833.11,102.04 ; 867.67,102.04 SW2.3@833.11,102.04 ; 967.53,178.81 SW1.1@1002.09,178.81 ; 1002.09,144.25 SW1.1@1002.09,178.81 ; 1002.09,213.38 SW1.1@1002.09,178.81 ; 1028.55,102.04 SW1.3@1063.11,102.04 ; 1036.65,178.81 SW1.1@1002.09,178.81 ; 1063.11,67.48 SW1.3@1063.11,102.04 ; 1063.11,136.6 SW1.3@1063.11,102.04 ; 1097.67,102.04 SW1.3@1063.11,102.04 ; 1152.7,532.79 SS7.1@1262.06,532.79 ; 1152.7,2343.81 SS5.1@1262.06,2343.81 ; 1249.89,145.66 J44.6@1278.54,145.66 ; 1262.06,423.43 SS7.1@1262.06,532.79 ; 1262.06,642.15 SS7.1@1262.06,532.79 ; 1262.06,2234.45 SS5.1@1262.06,2343.81 ; 1262.06,2453.17 SS5.1@1262.06,2343.81 ; 1278.54,117.01 J44.6@1278.54,145.66 ; 1278.54,174.32 J44.6@1278.54,145.66 ; 1307.2,145.66 J44.6@1278.54,145.66 ; 1371.42,532.79 SS7.1@1262.06,532.79 ; 1371.42,2343.81 SS5.1@1262.06,2343.81 ; 1407.37,145.66 J44.4@1436.02,145.66 ; 1436.02,117.01 J44.4@1436.02,145.66 ; 1436.02,174.32 J44.4@1436.02,145.66 ; 1464.68,145.66 J44.4@1436.02,145.66 ; 1564.85,145.66 J44.2@1593.5,145.66 ; 1593.5,117.01 J44.2@1593.5,145.66 ; 1593.5,174.32 J44.2@1593.5,145.66 ; 1622.16,145.66 J44.2@1593.5,145.66 ; 1812.29,3179.14 J7.10@1850.79,3179.14 ; 1841.07,145.66 J41.5@1869.72,145.66 ; 1850.79,3140.64 J7.10@1850.79,3179.14 ; 1850.79,3217.64 J7.10@1850.79,3179.14 ; 1869.72,117.01 J41.5@1869.72,145.66 ; 1869.72,174.32 J41.5@1869.72,145.66 ; 1889.29,3179.14 J7.10@1850.79,3179.14 ; 1898.38,145.66 J41.5@1869.72,145.66 ; 2474.17,159.06 J38.2@2509.72,159.06 ; 2509.72,123.51 J38.2@2509.72,159.06 ; 2509.72,194.6 J38.2@2509.72,159.06 ; 2536.7,3179.14 J6.10@2575.2,3179.14 ; 2545.27,159.06 J38.2@2509.72,159.06 ; 2574.17,159.06 J38.3@2609.72,159.06 ; 2575.2,3140.64 J6.10@2575.2,3179.14 ; 2575.2,3217.64 J6.10@2575.2,3179.14 ; 2609.72,123.51 J38.3@2609.72,159.06 ; 2609.72,194.6 J38.3@2609.72,159.06 ; 2613.7,3179.14 J6.10@2575.2,3179.14 ; 2645.27,159.06 J38.3@2609.72,159.06 ; 2867.52,127.95 J39.S1@2915.86,127.95 ; 2915.86,79.61 J39.S1@2915.86,127.95 ; 2915.86,176.29 J39.S1@2915.86,127.95 ; 2964.2,127.95 J39.S1@2915.86,127.95 ; 2992.32,108.27 J39.7@3020.98,108.27 ; 3020.98,79.61 J39.7@3020.98,108.27 ; 3020.98,136.92 J39.7@3020.98,108.27 ; 3049.64,108.27 J39.7@3020.98,108.27 ; 3142.32,108.27 J39.4@3170.98,108.27 ; 3170.98,79.61 J39.4@3170.98,108.27 ; 3170.98,136.92 J39.4@3170.98,108.27 ; 3199.64,108.27 J39.4@3170.98,108.27 ; 3292.32,108.27 J39.1@3320.98,108.27 ; 3320.98,79.61 J39.1@3320.98,108.27 ; 3320.98,136.92 J39.1@3320.98,108.27 ; 3334.97,3079.7 J16.17@3357.72,3079.7 3380.47,3079.7 ; 3334.97,3216.11 J16.11@3357.72,3216.11 3380.47,3216.11 ; 3334.97,3352.53 J16.5@3357.72,3352.53 3380.47,3352.53 ; 3349.64,108.27 J39.1@3320.98,108.27 ; 3374.34,3284.53 J16.8@3397.09,3284.53 3419.84,3284.53 ; 3374.34,3421.08 J16.2@3397.09,3421.08 ; 3377.76,127.95 J39.S2@3426.1,127.95 ; 3397.09,3443.83 J16.2@3397.09,3421.08 ; 3419.84,3421.08 J16.2@3397.09,3421.08 ; 3426.1,79.61 J39.S2@3426.1,127.95 ; 3426.1,176.29 J39.S2@3426.1,127.95 ; 3474.44,127.95 J39.S2@3426.1,127.95 ; 3751.13,532.79 SS8.1@3860.49,532.79 ; 3751.13,2343.81 SS6.1@3860.49,2343.81 ; 3760.16,3079.7 J17.17@3782.91,3079.7 3805.66,3079.7 ; 3760.16,3216.11 J17.11@3782.91,3216.11 3805.66,3216.11 ; 3760.16,3352.53 J17.5@3782.91,3352.53 3805.66,3352.53 ; 3799.53,3284.53 J17.8@3822.28,3284.53 3845.03,3284.53 ; 3799.53,3421.08 J17.2@3822.28,3421.08 ; 3822.28,3443.83 J17.2@3822.28,3421.08 ; 3845.03,3421.08 J17.2@3822.28,3421.08 ; 3860.49,423.43 SS8.1@3860.49,532.79 ; 3860.49,642.15 SS8.1@3860.49,532.79 ; 3860.49,2234.45 SS6.1@3860.49,2343.81 ; 3860.49,2453.17 SS6.1@3860.49,2343.81 ; 3969.85,532.79 SS8.1@3860.49,532.79 ; 3969.85,2343.81 SS6.1@3860.49,2343.81 ; 4137.72,493.42 J29.4@4166.38,493.42 ; 4166.38,464.76 J29.4@4166.38,493.42 ; 4166.38,522.08 J29.4@4166.38,493.42 ; 4185.36,3079.7 J18.17@4208.11,3079.7 4230.86,3079.7 ; 4185.36,3216.11 J18.11@4208.11,3216.11 4230.86,3216.11 ; 4185.36,3352.53 J18.5@4208.11,3352.53 4230.86,3352.53 ; 4191.86,1330.6 J12.2@4219.53,1330.6 ; 4195.03,493.42 J29.4@4166.38,493.42 ; 4219.53,1302.92 J12.2@4219.53,1330.6 ; 4219.53,1358.27 J12.2@4219.53,1330.6 ; 4224.73,3284.53 J18.8@4247.48,3284.53 4270.23,3284.53 ; 4224.73,3421.08 J18.2@4247.48,3421.08 ; 4247.2,1330.6 J12.2@4219.53,1330.6 ; 4247.48,3443.83 J18.2@4247.48,3421.08 ; 4270.23,3421.08 J18.2@4247.48,3421.08 ; 4385.71,1338.42 J26.2@4410.43,1338.42 ; 4410.43,1313.7 J26.2@4410.43,1338.42 ; 4410.43,1363.14 J26.2@4410.43,1338.42 ; 4429.97,728.11 J28.4@4458.62,728.11 ; 4458.62,699.45 J28.4@4458.62,728.11 ; 4458.62,756.77 J28.4@4458.62,728.11 ; 4487.28,728.11 J28.4@4458.62,728.11 ; 4638.66,509.17 SS9.1@4748.02,509.17 ; 4670.99,3274.86 J9.13@4699.64,3274.86 ; 4670.99,3400.86 J9.4@4699.64,3400.86 ; 4699.64,3246.21 J9.13@4699.64,3274.86 ; 4699.64,3303.52 J9.13@4699.64,3274.86 ; 4699.64,3372.21 J9.4@4699.64,3400.86 ; 4699.64,3429.52 J9.4@4699.64,3400.86 ; 4728.3,3274.86 J9.13@4699.64,3274.86 ; 4728.3,3400.86 J9.4@4699.64,3400.86 ; 4748.02,399.81 SS9.1@4748.02,509.17 ; 4748.02,618.53 SS9.1@4748.02,509.17 ; 4808.78,3215.77 J9.16@4837.44,3215.77 ; 4808.78,3341.77 J9.7@4837.44,3341.77 ; 4837.44,3187.11 J9.16@4837.44,3215.77 ; 4837.44,3244.42 J9.16@4837.44,3215.77 ; 4837.44,3313.11 J9.7@4837.44,3341.77 ; 4837.44,3370.42 J9.7@4837.44,3341.77 ; 4857.38,509.17 SS9.1@4748.02,509.17 ; 4866.1,3215.77 J9.16@4837.44,3215.77 ; 4866.1,3341.77 J9.7@4837.44,3341.77 ; 5076.3,238.19 J27.5@5118.74,238.19 ; 5118.74,195.75 J27.5@5118.74,238.19 ; 5118.74,280.62 J27.5@5118.74,238.19 ; 5120.05,1220.89 SS12.1@5229.41,1220.89 ; 5161.17,238.19 J27.5@5118.74,238.19 ; 5229.41,1111.52 SS12.1@5229.41,1220.89 ; 5229.41,1330.25 SS12.1@5229.41,1220.89 ; 5338.77,1220.89 SS12.1@5229.41,1220.89 ; 5378.82,3208.66 J10.4@5417.32,3208.66 ; 5378.82,3326.77 J10.10@5417.32,3326.77 ; 5417.32,3170.16 J10.4@5417.32,3208.66 ; 5417.32,3247.16 J10.4@5417.32,3208.66 ; 5417.32,3288.27 J10.10@5417.32,3326.77 ; 5417.32,3365.27 J10.10@5417.32,3326.77 ; 5455.82,3208.66 J10.4@5417.32,3208.66 ; 5455.82,3326.77 J10.10@5417.32,3326.77 ; 5526.3,238.19 J27.2@5568.74,238.19 ; 5568.74,195.75 J27.2@5568.74,238.19 ; 5568.74,280.62 J27.2@5568.74,238.19 ; 5591.42,509.17 SS10.1@5700.78,509.17 ; 5611.17,238.19 J27.2@5568.74,238.19 ; 5700.78,399.81 SS10.1@5700.78,509.17 ; 5700.78,618.53 SS10.1@5700.78,509.17 ; 5810.14,509.17 SS10.1@5700.78,509.17 ; 6230.88,136.22 SS11.1@6340.24,136.22 ; 6340.24,245.58 SS11.1@6340.24,136.22 ; 6449.6,136.22 SS11.1@6340.24,136.22
  ART03 w10: v1(422.74,30.68) v1(572.74,30.68) v1(722.74,30.68) v1(872.74,30.68) v1(1022.74,30.68) v1(1172.73,30.68) v1(1322.73,30.68) v1(1472.73,30.68) v1(1622.73,30.68) v1(1772.73,30.68) v1(1922.73,30.68) v1(2072.74,30.68) v1(2222.74,30.68) v1(2372.74,30.68) v1(2522.74,30.68) v1(2672.74,30.68) v1(2822.74,30.68) v1(2972.74,30.68) v1(3122.74,30.68) v1(3272.74,30.68) v1(3422.74,30.68) v1(3572.74,30.68) v1(3722.74,30.68) v1(3872.74,30.68) v1(4022.74,30.68) v1(4172.73,30.68) v1(4322.73,30.68) v1(4472.73,30.68) v1(4622.73,30.68) v1(4772.73,30.68) v1(4922.73,30.68) v1(5072.73,30.68) v1(5222.73,30.68) v1(5372.73,30.68) v1(5522.73,30.68) v1(5672.73,30.68) v1(5822.73,30.68) v1(5972.73,30.68) v1(6122.73,30.68) 6234.71,30.68 SS11.1@6340.24,136.22 ; v1(573.86,1703.74) v1(613.23,1703.74) ; v1(800,2705) v1(800,2740) 800,2826 ; v1(840,2705) v1(840,2740) ; v1(1045.63,1323.38) v1(1085,1323.38) v1(1124.37,1323.38) ; v1(1632.28,3748.84) v1(1671.65,3748.84) v1(1711.02,3748.84) v1(1750.39,3748.84) v1(1789.76,3748.84) v1(1829.13,3748.84) v1(1868.5,3748.84) v1(1907.87,3748.84) v1(1947.24,3748.84) v1(1986.61,3748.84) v1(2025.98,3748.84) v1(2065.35,3748.84) v1(2104.72,3748.84) v1(2144.09,3748.84) v1(2183.46,3748.84) v1(2222.83,3748.84) v1(2262.2,3748.84) v1(2301.57,3748.84) v1(2340.94,3748.84) v1(2380.31,3748.84) v1(2419.68,3748.84) v1(2459.05,3748.84) v1(2498.42,3748.84) v1(2537.79,3748.84) v1(2577.16,3748.84) v1(2616.53,3748.84) v1(2655.9,3748.84) v1(2695.27,3748.84) v1(2734.64,3748.84) v1(2774.01,3748.84) v1(2813.38,3748.84) v1(2852.75,3748.84) v1(2892.12,3748.84) v1(2931.49,3748.84) v1(2970.86,3748.84) v1(3010.23,3748.84) v1(3049.6,3748.84) v1(3088.97,3748.84) v1(3132.28,3748.84) v1(3196.06,3748.84) v1(3235.43,3748.84) v1(3274.8,3748.84) v1(3314.17,3748.84) v1(3353.54,3748.84) v1(3392.91,3748.84) v1(3432.28,3748.84) v1(3582.28,3748.84) v1(3614.17,3748.84) v1(3653.54,3748.84) v1(3692.91,3748.84) v1(3732.28,3748.84) v1(3771.65,3748.84) v1(3811.02,3748.84) v1(3882.28,3748.84) v1(4032.28,3748.84) v1(4182.28,3748.84) v1(4292.91,3748.84) v1(4332.28,3748.84) v1(4403.54,3748.84) v1(4442.91,3748.84) v1(4482.28,3748.84) v1(4632.28,3748.84) 4635.44,3752 5079.13,3752 v1(5082.28,3748.84) ; 2252,1090 v1(2450,1090) ; v1(2301,2183) 2329,2183 ; v1(2623.63,1479.74) 2637.89,1494 2661,1494 ; 4353.11,728.11 J28.4@4458.62,728.11 ; v1(6065,505) v1(6065,559.29) ; v1(6065,2851.58) v1(6065,2890.95) ; v1(6104.37,2851.58) v1(6104.37,2890.95) ; 6259.68,2878.32 v1(6259.68,2890.63) ; v1(6290.79,487.68) 6290.79,569.58 v1(6292,570.79) ; 6517.41,3015.59 v1(6527.5,3005.5)
  ART03 w15: 32.36,321.89 J25.3@70.86,321.89 ; 35.91,753.93 J20.B32@64.56,753.93 ; 64.56,725.28 J20.B32@64.56,753.93 ; 64.56,782.59 J20.B32@64.56,753.93 ; 70.86,283.39 J25.3@70.86,321.89 ; 70.86,360.38 J25.3@70.86,321.89 ; 93.22,753.93 J20.B32@64.56,753.93 ; 109.36,321.89 J25.3@70.86,321.89 ; 213.07,793.3 J20.A31@241.73,793.3 ; 213.07,1423.22 J20.A15@241.73,1423.22 ; 213.07,2053.14 J20.A1@241.73,2053.14 241.73,2024.49 ; 241.73,764.65 J20.A31@241.73,793.3 ; 241.73,1394.57 J20.A15@241.73,1423.22 ; 241.73,1451.88 J20.A15@241.73,1423.22 ; 270.38,793.3 J20.A31@241.73,793.3 ; 277.53,178.81 SW4.1@312.09,178.81 ; 291.81,1541.33 J20.A12@320.47,1541.33 ; 312.09,144.25 SW4.1@312.09,178.81 ; 312.09,213.38 SW4.1@312.09,178.81 ; 320.47,1512.68 J20.A12@320.47,1541.33 ; 320.47,1569.99 J20.A12@320.47,1541.33 ; 338.55,102.04 SW4.3@373.11,102.04 ; 346.65,178.81 SW4.1@312.09,178.81 ; 373.11,67.48 SW4.3@373.11,102.04 ; 373.11,136.6 SW4.3@373.11,102.04 ; 407.67,102.04 SW4.3@373.11,102.04 ; 447.72,3412.17 J5.2@476.37,3412.17 ; 476.37,3353.97 J5.2@476.37,3412.17 ; 476.37,3470.37 J5.2@476.37,3412.17 ; 505.02,3412.17 J5.2@476.37,3412.17 ; 507.53,178.81 SW3.1@542.09,178.81 ; 542.09,144.25 SW3.1@542.09,178.81 ; 542.09,213.38 SW3.1@542.09,178.81 ; 568.55,102.04 SW3.3@603.11,102.04 ; 576.65,178.81 SW3.1@542.09,178.81 ; 603.11,67.48 SW3.3@603.11,102.04 ; 603.11,136.6 SW3.3@603.11,102.04 ; 637.67,102.04 SW3.3@603.11,102.04 ; 656.32,3412.17 J5.3@684.97,3412.17 ; 684.97,3353.97 J5.3@684.97,3412.17 ; 684.97,3470.37 J5.3@684.97,3412.17 ; 713.62,3412.17 J5.3@684.97,3412.17 ; 772.09,144.25 SW2.1@772.09,178.81 ; 772.09,213.38 SW2.1@772.09,178.81 ; 798.55,102.04 SW2.3@833.11,102.04 ; 806.65,178.81 SW2.1@772.09,178.81 ; 833.11,136.6 SW2.3@833.11,102.04 ; 867.67,102.04 SW2.3@833.11,102.04 ; 967.53,178.81 SW1.1@1002.09,178.81 ; 1002.09,144.25 SW1.1@1002.09,178.81 ; 1028.55,102.04 SW1.3@1063.11,102.04 ; 1036.65,178.81 SW1.1@1002.09,178.81 ; 1063.11,136.6 SW1.3@1063.11,102.04 ; 1097.67,102.04 SW1.3@1063.11,102.04 ; 1152.7,532.79 SS7.1@1262.06,532.79 ; 1249.89,145.66 J44.6@1278.54,145.66 ; 1262.06,642.15 SS7.1@1262.06,532.79 ; 1278.54,117.01 J44.6@1278.54,145.66 ; 1278.54,174.32 J44.6@1278.54,145.66 ; 1307.2,145.66 J44.6@1278.54,145.66 ; 1371.42,532.79 SS7.1@1262.06,532.79 ; 1407.37,145.66 J44.4@1436.02,145.66 ; 1436.02,117.01 J44.4@1436.02,145.66 ; 1436.02,174.32 J44.4@1436.02,145.66 ; 1464.68,145.66 J44.4@1436.02,145.66 ; 1593.5,117.01 J44.2@1593.5,145.66 ; 1593.5,174.32 J44.2@1593.5,145.66 ; 1622.16,145.66 J44.2@1593.5,145.66 ; 3751.13,2343.81 SS6.1@3860.49,2343.81 ; 3860.49,2234.45 SS6.1@3860.49,2343.81 ; 3969.85,2343.81 SS6.1@3860.49,2343.81 ; 4670.99,3274.86 J9.13@4699.64,3274.86 ; 4670.99,3400.86 J9.4@4699.64,3400.86 ; 4699.64,3246.21 J9.13@4699.64,3274.86 ; 4699.64,3303.52 J9.13@4699.64,3274.86 ; 4699.64,3372.21 J9.4@4699.64,3400.86 ; 4699.64,3429.52 J9.4@4699.64,3400.86 ; 4728.3,3274.86 J9.13@4699.64,3274.86 ; 4728.3,3400.86 J9.4@4699.64,3400.86 ; 4808.78,3215.77 J9.16@4837.44,3215.77 ; 4808.78,3341.77 J9.7@4837.44,3341.77 ; 4837.44,3187.11 J9.16@4837.44,3215.77 ; 4837.44,3244.42 J9.16@4837.44,3215.77 ; 4837.44,3313.11 J9.7@4837.44,3341.77 ; 4837.44,3370.42 J9.7@4837.44,3341.77 ; 4866.1,3215.77 J9.16@4837.44,3215.77 ; 4866.1,3341.77 J9.7@4837.44,3341.77 ; 5378.82,3208.66 J10.4@5417.32,3208.66 ; 5378.82,3326.77 J10.10@5417.32,3326.77 ; 5417.32,3170.16 J10.4@5417.32,3208.66 ; 5417.32,3247.16 J10.4@5417.32,3208.66 ; 5417.32,3288.27 J10.10@5417.32,3326.77 ; 5417.32,3365.27 J10.10@5417.32,3326.77 ; 5455.82,3208.66 J10.4@5417.32,3208.66 ; 5455.82,3326.77 J10.10@5417.32,3326.77 ; 6230.88,136.22 SS11.1@6340.24,136.22 ; 6340.24,245.58 SS11.1@6340.24,136.22 ; 6449.6,136.22 SS11.1@6340.24,136.22
  ART04 w10: v1(30.68,3188.49) v1(30.68,3038.49) v1(30.68,2888.49) v1(30.68,2738.49) v1(30.68,2588.49) v1(30.68,2438.49) v1(30.68,2288.49) v1(30.68,2138.49) 25,2132.8 25,367.75 J25.3@70.86,321.89 ; v1(872.74,30.68) v1(1022.74,30.68) v1(1172.73,30.68) v1(1322.73,30.68) v1(1472.73,30.68) v1(1622.73,30.68) v1(1772.73,30.68) v1(1922.73,30.68) v1(2072.74,30.68) v1(2222.74,30.68) v1(2372.74,30.68) v1(2522.74,30.68) v1(2672.74,30.68) v1(2822.74,30.68) v1(2972.74,30.68) v1(3122.74,30.68) v1(3272.74,30.68) v1(3422.74,30.68) v1(3572.74,30.68) v1(3722.74,30.68) v1(3872.74,30.68) v1(4022.74,30.68) v1(4172.73,30.68) v1(4322.73,30.68) v1(4472.73,30.68) v1(4622.73,30.68) v1(4772.73,30.68) v1(4922.73,30.68) v1(5072.73,30.68) v1(5222.73,30.68) v1(5372.73,30.68) v1(5522.73,30.68) v1(5672.73,30.68) v1(5822.73,30.68) v1(5972.73,30.68) v1(6122.73,30.68) 6234.71,30.68 SS11.1@6340.24,136.22 6472.78,136.22 ; v1(2364,2078) 2376,2078 ; SS6.1@3860.49,2343.81 3860.49,2557.49 ; v1(4125,320) 4141,320 ; v1(4632.28,3748.84) v1(5082.28,3748.84) ; v1(5376,2477) 5392,2477 ; 5555,3500 v1(5555,3539) ; 5594.37,3500 v1(5594.37,3539) ; 5633.74,3500 v1(5633.74,3539) ; 6343,2654.37 v1(6375,2654.37) ; 6343,2697 v1(6372,2697) ; 6343,2743 v1(6373,2743) ; v1(6564.72,3061.89) 6590.26,3061.89 ; v1(6564.72,3101.26) 6590.26,3101.26 ; v1(6564.72,3140.63) 6590.26,3140.63 ; v1(6564.72,3180) 6590.26,3180 ; v1(6564.72,3219.37) 6590.26,3219.37 ; v1(6564.72,3258.74) 6590.26,3258.74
